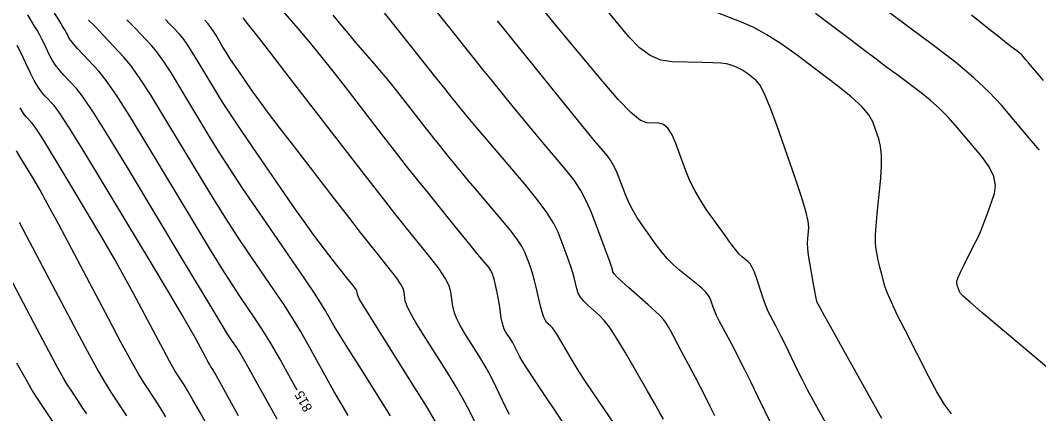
# Model space of a CAD drawing. Extents: x 2082232 to 2083549, y 592624 to 593832.
# Drawn here: x 2082374.1 to 2082448.2, y 593196.8 to 593225.4 of the extents above; entities that cross this region are included whole.
import ezdxf

# ---------------------------------------------------------------- set-up
doc = ezdxf.new("R2010")
doc.units = 0
doc.layers.add('DT_X_Contour_Major', color=7, linetype='Continuous')
doc.layers.add('DT_X_Contour_Minor', color=7, linetype='Continuous')

msp = doc.modelspace()

# ---------------------------------------------------------------- linework, layer by layer
at = {"layer": 'DT_X_Contour_Major'}
for points in [[(2082448.254, 593215.971), (2082447.537, 593216.821), (2082445.493, 593219.244), (2082444.61, 593220.197), (2082443.492, 593221.241), (2082442.139, 593222.376), (2082440.552, 593223.6), (2082436.008, 593226.986)], [(2082394.247, 593198.485), (2082393.791, 593199.31), (2082392.976, 593200.763), (2082392.272, 593201.978), (2082391.68, 593202.954), (2082391.198, 593203.692), (2082390.061, 593205.343), (2082389.528, 593206.152), (2082388.781, 593207.338), (2082387.822, 593208.904), (2082386.648, 593210.848), (2082383.235, 593216.536), (2082382.061, 593218.46), (2082381.097, 593219.967), (2082380.344, 593221.056), (2082379.803, 593221.727), (2082378.639, 593222.961), (2082378.251, 593223.379), (2082377.959, 593223.708), (2082377.763, 593223.949), (2082377.664, 593224.101), (2082377.526, 593224.387), (2082377.452, 593224.528), (2082377.334, 593224.736), (2082377.171, 593225.012), (2082376.964, 593225.355), (2082376.352, 593226.359)], [(2082409.696, 593196.722), (2082409.416, 593197.279), (2082408.733, 593198.72), (2082408.462, 593199.268), (2082408.159, 593199.833), (2082407.824, 593200.413), (2082407.458, 593201.01), (2082406.439, 593202.622), (2082406.099, 593203.199), (2082405.841, 593203.723), (2082405.665, 593204.192), (2082405.572, 593204.608), (2082405.435, 593205.644), (2082405.304, 593206.09), (2082405.015, 593206.651), (2082404.568, 593207.326), (2082403.963, 593208.117), (2082402.138, 593210.379), (2082401.349, 593211.367), (2082400.351, 593212.637), (2082399.143, 593214.188), (2082397.726, 593216.021), (2082393.669, 593221.283), (2082392.317, 593223.033), (2082391.305, 593224.336), (2082390.634, 593225.193), (2082390.303, 593225.603)], [(2082429.265, 593194.955), (2082427.798, 593197.987), (2082427.278, 593199.054), (2082426.819, 593199.982), (2082426.42, 593200.77), (2082426.082, 593201.418), (2082425.262, 593202.961), (2082424.984, 593203.494), (2082424.766, 593203.935), (2082424.608, 593204.285), (2082424.509, 593204.543), (2082424.326, 593205.109), (2082424.209, 593205.34), (2082423.996, 593205.609), (2082423.686, 593205.917), (2082423.28, 593206.264), (2082422.068, 593207.238), (2082421.622, 593207.627), (2082421.19, 593208.063), (2082420.774, 593208.547), (2082420.372, 593209.077), (2082419.323, 593210.555), (2082418.955, 593211.103), (2082418.638, 593211.638), (2082418.371, 593212.16), (2082418.156, 593212.669), (2082417.649, 593214.011), (2082417.454, 593214.484), (2082417.251, 593214.899), (2082417.039, 593215.254), (2082416.818, 593215.549), (2082416.216, 593216.259), (2082415.891, 593216.651), (2082415.366, 593217.293), (2082414.641, 593218.185), (2082413.717, 593219.328), (2082410.986, 593222.71), (2082410.043, 593223.878), (2082409.263, 593224.846), (2082408.818, 593225.401)], [(2082381.849, 593196.632), (2082380.718, 593198.345), (2082380.244, 593199.104), (2082379.668, 593200.096), (2082378.99, 593201.32), (2082378.211, 593202.776), (2082375.999, 593206.97), (2082375.227, 593208.433), (2082374.571, 593209.676), (2082374.031, 593210.699)]]:
    msp.add_lwpolyline(points, dxfattribs=at)
at = {"layer": 'DT_X_Contour_Minor'}
for points in [[(2082414.193, 593195.272), (2082412.148, 593198.292), (2082411.466, 593199.306), (2082410.955, 593200.082), (2082410.613, 593200.621), (2082410.442, 593200.922), (2082410.211, 593201.409), (2082410.119, 593201.594), (2082410.017, 593201.784), (2082409.904, 593201.98), (2082409.781, 593202.182), (2082409.437, 593202.726), (2082409.319, 593202.942), (2082409.223, 593203.182), (2082409.15, 593203.446), (2082409.099, 593203.734), (2082408.993, 593204.533), (2082408.951, 593204.825), (2082408.905, 593205.103), (2082408.854, 593205.365), (2082408.799, 593205.613), (2082408.647, 593206.254), (2082408.593, 593206.474), (2082408.546, 593206.655), (2082408.505, 593206.796), (2082408.471, 593206.897), (2082408.39, 593207.113), (2082408.342, 593207.209), (2082408.259, 593207.334), (2082408.142, 593207.489), (2082407.99, 593207.674), (2082407.539, 593208.206), (2082407.3, 593208.494), (2082406.92, 593208.958), (2082406.4, 593209.599), (2082405.74, 593210.416), (2082403.792, 593212.831), (2082403.031, 593213.78), (2082402.211, 593214.818), (2082401.331, 593215.943), (2082400.391, 593217.156), (2082397.806, 593220.509), (2082396.86, 593221.722), (2082395.963, 593222.846), (2082395.115, 593223.88), (2082394.315, 593224.825), (2082392.246, 593227.227)], [(2082424.643, 593196.625), (2082424.308, 593197.309), (2082423.96, 593198.001), (2082423.599, 593198.702), (2082423.226, 593199.412), (2082422.214, 593201.317), (2082421.87, 593201.961), (2082421.601, 593202.464), (2082421.404, 593202.826), (2082421.281, 593203.046), (2082421.051, 593203.447), (2082420.907, 593203.637), (2082420.65, 593203.909), (2082420.28, 593204.263), (2082419.795, 593204.698), (2082418.352, 593205.966), (2082417.876, 593206.395), (2082417.529, 593206.729), (2082417.311, 593206.97), (2082417.223, 593207.116), (2082417.16, 593207.38), (2082417.1, 593207.57), (2082416.969, 593207.942), (2082416.765, 593208.495), (2082416.489, 593209.229), (2082415.657, 593211.431), (2082415.309, 593212.242), (2082414.887, 593213.026), (2082414.392, 593213.782), (2082413.823, 593214.51), (2082412.21, 593216.415), (2082411.609, 593217.128), (2082411.018, 593217.838), (2082410.436, 593218.545), (2082409.864, 593219.249), (2082408.35, 593221.123), (2082407.76, 593221.856), (2082407.124, 593222.65), (2082406.443, 593223.503), (2082405.717, 593224.417), (2082403.721, 593226.933)], [(2082436.796, 593196.417), (2082434.147, 593201.17), (2082433.277, 593202.731), (2082432.654, 593203.849), (2082432.278, 593204.525), (2082432.148, 593204.758), (2082432.127, 593204.802), (2082432.122, 593204.812), (2082432.118, 593204.82), (2082432.115, 593204.827), (2082432.106, 593204.843), (2082432.102, 593204.852), (2082432.097, 593204.866), (2082432.09, 593204.886), (2082432.082, 593204.91), (2082432.058, 593204.983), (2082432.037, 593205.08), (2082431.992, 593205.317), (2082431.923, 593205.693), (2082431.829, 593206.209), (2082431.547, 593207.77), (2082431.458, 593208.32), (2082431.404, 593208.8), (2082431.383, 593209.208), (2082431.396, 593209.545), (2082431.475, 593210.35), (2082431.438, 593210.797), (2082431.264, 593211.535), (2082430.955, 593212.562), (2082430.509, 593213.88), (2082429.141, 593217.781), (2082428.664, 593219.083), (2082428.257, 593220.063), (2082427.92, 593220.721), (2082427.654, 593221.056), (2082427.038, 593221.522), (2082426.814, 593221.683), (2082426.604, 593221.818), (2082426.407, 593221.926), (2082426.224, 593222.007), (2082425.753, 593222.189), (2082425.495, 593222.251), (2082425.074, 593222.299), (2082424.49, 593222.335), (2082423.744, 593222.357), (2082421.536, 593222.4), (2082420.72, 593222.525), (2082419.925, 593222.868), (2082419.154, 593223.429), (2082418.405, 593224.208), (2082416.437, 593226.576)], [(2082392.779, 593196.382), (2082391.259, 593199.127), (2082390.744, 593200.053), (2082390.336, 593200.772), (2082390.036, 593201.284), (2082389.843, 593201.588), (2082389.475, 593202.123), (2082389.161, 593202.621), (2082388.493, 593203.715), (2082387.472, 593205.405), (2082386.099, 593207.69), (2082381.965, 593214.579), (2082380.566, 593216.885), (2082379.469, 593218.636), (2082378.673, 593219.832), (2082378.179, 593220.473), (2082377.264, 593221.443), (2082376.944, 593221.803), (2082376.669, 593222.156), (2082376.44, 593222.501), (2082376.257, 593222.839), (2082375.829, 593223.731), (2082375.665, 593224.062), (2082375.494, 593224.386), (2082375.317, 593224.703), (2082375.134, 593225.014), (2082374.635, 593225.832)], [(2082417.336, 593196.003), (2082415.777, 593198.306), (2082415.233, 593199.117), (2082414.773, 593199.822), (2082414.395, 593200.421), (2082414.1, 593200.914), (2082413.423, 593202.089), (2082413.188, 593202.486), (2082412.99, 593202.796), (2082412.828, 593203.02), (2082412.703, 593203.157), (2082412.419, 593203.406), (2082412.311, 593203.553), (2082412.198, 593203.804), (2082412.082, 593204.16), (2082411.962, 593204.62), (2082411.637, 593205.989), (2082411.514, 593206.479), (2082411.391, 593206.924), (2082411.268, 593207.322), (2082411.144, 593207.674), (2082410.812, 593208.552), (2082410.618, 593208.941), (2082410.283, 593209.451), (2082409.807, 593210.08), (2082409.191, 593210.83), (2082407.361, 593212.99), (2082406.722, 593213.747), (2082406.175, 593214.4), (2082405.721, 593214.947), (2082405.36, 593215.389), (2082404.521, 593216.429), (2082404.193, 593216.838), (2082403.84, 593217.285), (2082403.461, 593217.769), (2082403.057, 593218.292), (2082401.943, 593219.736), (2082401.508, 593220.29), (2082401.04, 593220.869), (2082400.537, 593221.474), (2082400.001, 593222.104), (2082398.525, 593223.818), (2082397.972, 593224.467), (2082397.42, 593225.128), (2082396.869, 593225.802)], [(2082420.905, 593196.389), (2082420.646, 593196.844), (2082420.249, 593197.536), (2082419.714, 593198.466), (2082418.104, 593201.261), (2082417.536, 593202.214), (2082417.037, 593202.976), (2082416.608, 593203.547), (2082416.249, 593203.927), (2082415.386, 593204.686), (2082415.093, 593204.974), (2082414.863, 593205.267), (2082414.697, 593205.565), (2082414.592, 593205.868), (2082414.398, 593206.685), (2082414.307, 593207.025), (2082414.18, 593207.433), (2082414.016, 593207.908), (2082413.817, 593208.452), (2082413.235, 593209.991), (2082412.921, 593210.642), (2082412.415, 593211.439), (2082411.718, 593212.381), (2082410.829, 593213.471), (2082408.203, 593216.57), (2082407.327, 593217.604), (2082406.67, 593218.382), (2082406.231, 593218.904), (2082406.011, 593219.17), (2082405.714, 593219.537), (2082405.476, 593219.835), (2082404.985, 593220.453), (2082404.24, 593221.391), (2082403.242, 593222.649), (2082400.241, 593226.432)], [(2082433.703, 593194.33), (2082432.309, 593196.831), (2082431.817, 593197.724), (2082431.385, 593198.526), (2082431.016, 593199.236), (2082430.707, 593199.856), (2082429.965, 593201.389), (2082429.703, 593201.928), (2082429.471, 593202.397), (2082429.269, 593202.795), (2082429.098, 593203.123), (2082428.684, 593203.902), (2082428.529, 593204.217), (2082428.375, 593204.574), (2082428.223, 593204.976), (2082428.071, 593205.421), (2082427.668, 593206.666), (2082427.516, 593207.09), (2082427.361, 593207.43), (2082427.204, 593207.686), (2082427.045, 593207.857), (2082426.617, 593208.201), (2082426.416, 593208.399), (2082426.135, 593208.735), (2082425.773, 593209.209), (2082425.33, 593209.82), (2082424.042, 593211.634), (2082423.585, 593212.322), (2082423.181, 593213.025), (2082422.83, 593213.743), (2082422.531, 593214.475), (2082421.805, 593216.45), (2082421.523, 593217.099), (2082421.224, 593217.564), (2082420.907, 593217.846), (2082420.572, 593217.944), (2082419.655, 593217.962), (2082419.199, 593218.155), (2082418.519, 593218.719), (2082417.614, 593219.655), (2082416.484, 593220.963), (2082413.174, 593224.947), (2082412.087, 593226.255)], [(2082441.852, 593196.762), (2082441.347, 593197.456), (2082440.79, 593198.373), (2082440.18, 593199.513), (2082438.485, 593202.849), (2082437.916, 593203.988), (2082437.483, 593204.903), (2082437.183, 593205.594), (2082437.019, 593206.061), (2082436.759, 593207.007), (2082436.669, 593207.349), (2082436.591, 593207.666), (2082436.525, 593207.958), (2082436.473, 593208.225), (2082436.35, 593208.904), (2082436.322, 593209.248), (2082436.329, 593209.769), (2082436.372, 593210.469), (2082436.45, 593211.346), (2082436.706, 593213.924), (2082436.769, 593214.828), (2082436.768, 593215.606), (2082436.703, 593216.259), (2082436.572, 593216.786), (2082436.138, 593218.024), (2082435.854, 593218.537), (2082435.33, 593219.147), (2082434.564, 593219.854), (2082433.557, 593220.658), (2082430.551, 593222.931), (2082429.457, 593223.718), (2082428.428, 593224.376), (2082427.467, 593224.903), (2082426.571, 593225.301), (2082424.27, 593226.19)], [(2082448.803, 593200.158), (2082445.247, 593203.16), (2082444.077, 593204.153), (2082443.231, 593204.881), (2082442.71, 593205.344), (2082442.514, 593205.542), (2082442.424, 593205.718), (2082442.392, 593205.787), (2082442.361, 593205.863), (2082442.333, 593205.946), (2082442.306, 593206.036), (2082442.238, 593206.285), (2082442.251, 593206.436), (2082442.34, 593206.701), (2082442.505, 593207.08), (2082442.748, 593207.574), (2082443.495, 593209.043), (2082443.765, 593209.597), (2082444.015, 593210.155), (2082444.243, 593210.719), (2082444.451, 593211.288), (2082444.977, 593212.811), (2082445.068, 593213.409), (2082444.944, 593214.058), (2082444.607, 593214.76), (2082444.055, 593215.514), (2082442.3, 593217.595), (2082441.641, 593218.34), (2082440.98, 593219.014), (2082440.316, 593219.617), (2082439.65, 593220.15), (2082437.872, 593221.475), (2082437.166, 593222.002), (2082436.383, 593222.59), (2082435.521, 593223.238), (2082434.581, 593223.948), (2082431.972, 593225.92)], [(2082448.545, 593221.054), (2082447.892, 593221.832), (2082447.47, 593222.333), (2082447.281, 593222.559), (2082447.085, 593222.791), (2082447, 593222.882), (2082446.893, 593222.983), (2082446.763, 593223.091), (2082446.611, 593223.209), (2082446.175, 593223.534), (2082445.873, 593223.766), (2082445.295, 593224.221), (2082444.441, 593224.898), (2082443.31, 593225.798)], [(2082397.966, 593196.654), (2082397.442, 593197.528), (2082396.92, 593198.426), (2082396.4, 593199.35), (2082395.018, 593201.848), (2082394.475, 593202.798), (2082393.883, 593203.772), (2082393.242, 593204.772), (2082392.552, 593205.797), (2082390.647, 593208.564), (2082389.895, 593209.682), (2082389.07, 593210.962), (2082388.171, 593212.403), (2082387.198, 593214.005), (2082384.505, 593218.493), (2082383.569, 593220.021), (2082382.78, 593221.24), (2082382.138, 593222.15), (2082381.643, 593222.751), (2082380.521, 593223.942), (2082380.136, 593224.348), (2082379.823, 593224.676), (2082379.582, 593224.924), (2082379.413, 593225.094), (2082379.059, 593225.439)], [(2082401.047, 593196.611), (2082398.748, 593200.251), (2082397.973, 593201.483), (2082397.371, 593202.449), (2082396.944, 593203.149), (2082396.69, 593203.583), (2082396.245, 593204.387), (2082395.974, 593204.832), (2082395.494, 593205.567), (2082394.804, 593206.59), (2082393.906, 593207.902), (2082391.232, 593211.785), (2082390.262, 593213.213), (2082389.358, 593214.585), (2082388.52, 593215.901), (2082387.747, 593217.162), (2082385.775, 593220.449), (2082385.089, 593221.569), (2082384.511, 593222.462), (2082384.041, 593223.128), (2082383.679, 593223.569), (2082382.856, 593224.441), (2082382.539, 593224.774), (2082382.201, 593225.119), (2082381.845, 593225.476)], [(2082404.361, 593196.1), (2082403.644, 593197.321), (2082402.813, 593198.666), (2082400.445, 593202.413), (2082399.667, 593203.653), (2082399.108, 593204.562), (2082398.768, 593205.139), (2082398.648, 593205.386), (2082398.619, 593205.602), (2082398.592, 593205.694), (2082398.532, 593205.811), (2082398.439, 593205.952), (2082398.313, 593206.116), (2082397.933, 593206.587), (2082397.76, 593206.804), (2082397.526, 593207.103), (2082397.23, 593207.483), (2082396.874, 593207.944), (2082395.842, 593209.282), (2082395.394, 593209.88), (2082394.824, 593210.67), (2082394.132, 593211.652), (2082393.318, 593212.826), (2082390.985, 593216.214), (2082390.161, 593217.423), (2082389.439, 593218.51), (2082388.817, 593219.476), (2082388.297, 593220.319), (2082387.045, 593222.406), (2082386.61, 593223.117), (2082386.243, 593223.683), (2082385.944, 593224.107), (2082385.714, 593224.386), (2082385.192, 593224.939), (2082384.962, 593225.179), (2082384.662, 593225.482)], [(2082407.256, 593196.031), (2082406.804, 593196.943), (2082406.3, 593197.881), (2082405.744, 593198.846), (2082405.135, 593199.838), (2082403.442, 593202.517), (2082402.883, 593203.426), (2082402.474, 593204.142), (2082402.217, 593204.666), (2082402.11, 593204.997), (2082402.027, 593205.623), (2082401.948, 593205.892), (2082401.773, 593206.231), (2082401.503, 593206.639), (2082401.138, 593207.117), (2082400.036, 593208.483), (2082399.534, 593209.113), (2082398.854, 593209.979), (2082397.997, 593211.082), (2082396.963, 593212.42), (2082393.968, 593216.303), (2082392.939, 593217.645), (2082392.097, 593218.758), (2082391.444, 593219.641), (2082390.979, 593220.295), (2082389.988, 593221.733), (2082389.638, 593222.247), (2082389.331, 593222.708), (2082389.067, 593223.118), (2082388.846, 593223.477), (2082388.315, 593224.363), (2082388.13, 593224.664), (2082387.974, 593224.905), (2082387.847, 593225.085), (2082387.75, 593225.203), (2082387.528, 593225.438)], [(2082389.982, 593196.631), (2082389.209, 593198.032), (2082388.639, 593199.059), (2082388.272, 593199.714), (2082388.108, 593199.995), (2082387.941, 593200.249), (2082387.86, 593200.381), (2082387.743, 593200.589), (2082387.589, 593200.871), (2082387.399, 593201.228), (2082386.845, 593202.279), (2082386.487, 593202.917), (2082385.83, 593204.042), (2082384.873, 593205.654), (2082383.617, 593207.754), (2082379.867, 593214.003), (2082378.605, 593216.087), (2082377.633, 593217.65), (2082376.95, 593218.695), (2082376.555, 593219.219), (2082375.889, 593219.925), (2082375.637, 593220.227), (2082375.38, 593220.603), (2082375.118, 593221.054), (2082374.851, 593221.578), (2082374.131, 593223.075), (2082373.878, 593223.596)], [(2082387.841, 593195.68), (2082387.183, 593196.869), (2082386.66, 593197.798), (2082386.272, 593198.466), (2082386.021, 593198.874), (2082385.533, 593199.614), (2082385.297, 593200.001), (2082384.955, 593200.606), (2082384.507, 593201.43), (2082383.952, 593202.472), (2082382.333, 593205.542), (2082381.691, 593206.733), (2082380.981, 593208.003), (2082380.203, 593209.353), (2082379.356, 593210.781), (2082377.007, 593214.697), (2082376.216, 593216.002), (2082375.607, 593216.982), (2082375.179, 593217.637), (2082374.932, 593217.965), (2082374.514, 593218.408), (2082374.33, 593218.652), (2082374.09, 593219.051)], [(2082384.68, 593196.537), (2082384.273, 593197.219), (2082383.935, 593197.753), (2082383.126, 593198.98), (2082382.734, 593199.621), (2082382.167, 593200.624), (2082381.424, 593201.99), (2082380.505, 593203.717), (2082377.821, 593208.806), (2082376.896, 593210.549), (2082376.133, 593211.965), (2082375.533, 593213.051), (2082375.096, 593213.809), (2082374.146, 593215.391), (2082373.827, 593215.918)], [(2082378.938, 593196.76), (2082378.562, 593197.329), (2082378.256, 593197.794), (2082378.017, 593198.154), (2082377.848, 593198.41), (2082377.487, 593198.952), (2082377.251, 593199.353), (2082376.812, 593200.149), (2082376.173, 593201.34), (2082375.331, 593202.925), (2082372.818, 593207.681)], [(2082376.75, 593195.781), (2082375.494, 593197.668), (2082374.996, 593198.45), (2082374.444, 593199.381), (2082373.838, 593200.459)]]:
    msp.add_lwpolyline(points, dxfattribs=at)

# ---------------------------------------------------------------- texts
at = {"layer": 'DT_X_Contour_Major'}
msp.add_text('815', height=0.7, rotation=118.96229, dxfattribs=at).set_placement((2082395.381, 593197.159))

doc.saveas('drawing.dxf')
